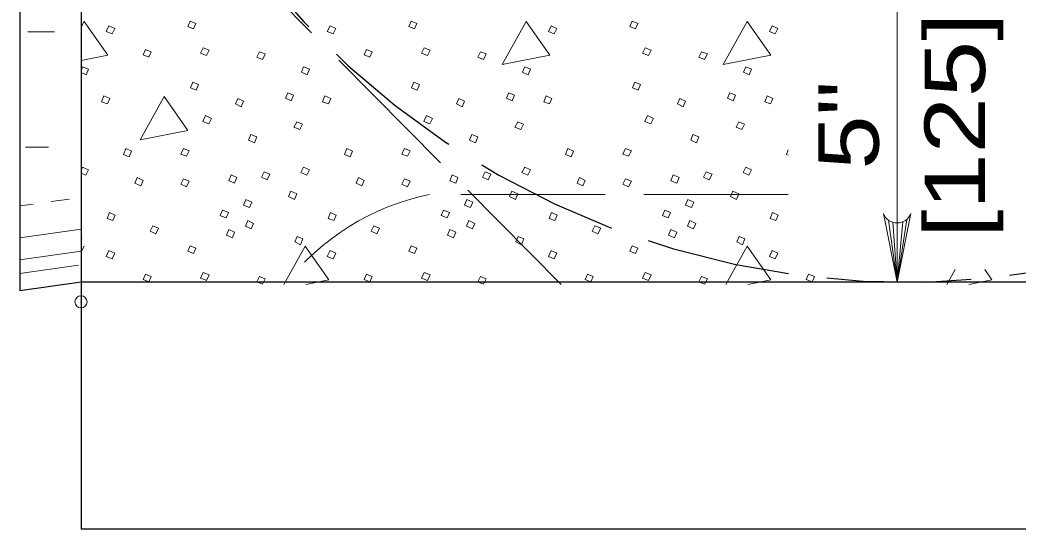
# Model space of a CAD drawing. Extents: x 1036.7 to 1070.7, y 883.9 to 905.9.
# Drawn here: x 1058.066 to 1060.639, y 886.963 to 888.275 of the extents above; entities that cross this region are included whole.
import ezdxf
from ezdxf.enums import TextEntityAlignment as Align

# ---------------------------------------------------------------- set-up
doc = ezdxf.new("R2010")
doc.units = 0
doc.header["$LTSCALE"] = 0.062
doc.header["$PDMODE"] = 32
doc.header["$PDSIZE"] = 0.031
doc.linetypes.add('LONG_DASHED', pattern=[7.5, 6, -1.5])
doc.layers.add('1', color=7, linetype='Continuous', lineweight=13)

msp = doc.modelspace()

# ---------------------------------------------------------------- linework, layer by layer
at = {"layer": '1', "lineweight": 25}
for p, q in [((1058.22342, 892.494), (1058.22342, 886.96275)), ((1058.06608, 891.88667), (1058.06608, 887.57675)), ((1058.22342, 887.59908), (1058.06608, 887.57675)), ((1062.47975, 887.59908), (1058.22342, 887.59908)), ((1062.47975, 886.96275), (1058.22342, 886.96275))]:
    msp.add_line(p, q, dxfattribs=at)
at = {"layer": '1', "linetype": 'LONG_DASHED'}
for p, q in [((1058.22342, 888.84183), (1059.461, 887.59333)), ((1060.0465, 887.82533), (1059.11317, 887.82533))]:
    msp.add_line(p, q, dxfattribs=at)
at = {"layer": '1'}
for p, q in [((1060.32708, 888.49858), (1060.32708, 888.19758)), ((1058.23167, 888.27158), (1058.22342, 888.25683)), ((1058.08675, 888.24467), (1058.15533, 888.24467)), ((1058.68342, 888.19367), (1058.69792, 888.18792)), ((1060.32708, 887.59908), (1060.32708, 888.19758)), ((1058.22342, 888.14475), (1058.22767, 888.15467)), ((1058.08058, 887.94742), (1058.13975, 887.94742)), ((1058.22342, 887.88733), (1058.22767, 887.89583)), ((1058.6105, 887.87583), (1058.61358, 887.87442)), ((1058.19292, 887.81375), (1058.14617, 887.80708)), ((1058.10025, 887.80058), (1058.06608, 887.79575)), ((1058.5885, 887.78492), (1058.58942, 887.78458)), ((1060.30467, 887.75933), (1060.32708, 887.59908)), ((1060.31575, 887.75392), (1060.32708, 887.59908)), ((1060.35183, 887.76117), (1060.32708, 887.59908)), ((1060.3415, 887.75508), (1060.32708, 887.59908)), ((1060.32708, 887.75225), (1060.32708, 887.59908)), ((1058.22342, 887.73558), (1058.06608, 887.71325)), ((1058.22342, 887.67933), (1058.06608, 887.657)), ((1058.23167, 887.69192), (1058.22342, 887.67717)), ((1058.80133, 887.69192), (1058.74633, 887.59333)), ((1059.94083, 887.69192), (1059.88575, 887.59333)), ((1058.21708, 887.64325), (1058.06608, 887.62192)), ((1058.5385, 887.624), (1058.54542, 887.62125)), ((1060.47683, 887.63158), (1060.4555, 887.59333))]:
    msp.add_line(p, q, dxfattribs=at)
for points in [[(1058.22342, 888.17117), (1058.29258, 888.18467), (1058.23167, 888.27158)], [(1058.69708, 888.18492), (1058.69142, 888.17367), (1058.67642, 888.17967), (1058.68342, 888.19367)], [(1058.69792, 888.18792), (1058.69842, 888.18767), (1058.69717, 888.18508), (1058.69708, 888.18492)], [(1058.22767, 888.15467), (1058.24267, 888.14867), (1058.23667, 888.13367), (1058.22342, 888.13983)], [(1058.22342, 888.00725), (1058.22467, 888.00675), (1058.22342, 888.00425)], [(1060.0465, 887.92692), (1060.04175, 887.92883), (1060.0465, 887.94058)], [(1058.22767, 887.89583), (1058.24267, 887.88883), (1058.23567, 887.87483), (1058.22342, 887.88058)], [(1058.60942, 887.85883), (1058.6045, 887.86083), (1058.6105, 887.87583)], [(1058.61358, 887.87442), (1058.62542, 887.86883), (1058.61942, 887.85483), (1058.60942, 887.85883)], [(1058.58542, 887.76975), (1058.5825, 887.77092), (1058.5885, 887.78492)], [(1058.58942, 887.78458), (1058.6035, 887.77892), (1058.5975, 887.76492), (1058.58542, 887.76975)], [(1060.3625, 887.77608), (1060.32708, 887.59908), (1060.29167, 887.77608)], [(1058.22342, 887.71183), (1058.22567, 887.71092), (1058.22342, 887.70533)], [(1058.80258, 887.59333), (1058.86233, 887.605), (1058.80133, 887.69192)], [(1059.94208, 887.59333), (1060.00183, 887.605), (1059.94083, 887.69192)], [(1058.54133, 887.60608), (1058.5315, 887.61), (1058.5385, 887.624)], [(1060.51183, 887.59333), (1060.5715, 887.605), (1060.55292, 887.63158)], [(1058.54542, 887.62125), (1058.5535, 887.618), (1058.5465, 887.604), (1058.54133, 887.60608)]]:
    msp.add_lwpolyline(points, dxfattribs=at)
for points in [[(1058.5045, 888.27258), (1058.5195, 888.26658), (1058.5135, 888.25258), (1058.4985, 888.25858)], [(1059.07425, 888.27258), (1059.08925, 888.26658), (1059.08325, 888.25258), (1059.06825, 888.25858)], [(1059.37108, 888.27158), (1059.30917, 888.16067), (1059.43208, 888.18467)], [(1059.644, 888.27258), (1059.659, 888.26658), (1059.653, 888.25258), (1059.638, 888.25858)], [(1059.94083, 888.27158), (1059.87883, 888.16067), (1060.00183, 888.18467)], [(1058.29558, 888.26058), (1058.31058, 888.25358), (1058.30358, 888.23958), (1058.28858, 888.24558)], [(1058.86533, 888.26058), (1058.88033, 888.25358), (1058.87333, 888.23958), (1058.85833, 888.24558)], [(1059.43508, 888.26058), (1059.45008, 888.25358), (1059.44308, 888.23958), (1059.42808, 888.24558)], [(1060.00483, 888.26058), (1060.01983, 888.25358), (1060.01283, 888.23958), (1059.99783, 888.24558)], [(1058.38958, 888.19967), (1058.40458, 888.19367), (1058.39858, 888.17967), (1058.38358, 888.18567)], [(1058.5385, 888.20367), (1058.5535, 888.19767), (1058.5465, 888.18367), (1058.5315, 888.18967)], [(1058.95933, 888.19967), (1058.97433, 888.19367), (1058.96833, 888.17967), (1058.95333, 888.18567)], [(1059.10825, 888.20367), (1059.12325, 888.19767), (1059.11625, 888.18367), (1059.10125, 888.18967)], [(1059.25317, 888.19367), (1059.26817, 888.18767), (1059.26117, 888.17367), (1059.24617, 888.17967)], [(1059.67792, 888.20367), (1059.69292, 888.19767), (1059.68592, 888.18367), (1059.671, 888.18967)], [(1059.82292, 888.19367), (1059.83792, 888.18767), (1059.83092, 888.17367), (1059.81592, 888.17967)], [(1058.79733, 888.15467), (1058.81233, 888.14867), (1058.80633, 888.13367), (1058.79142, 888.14067)], [(1059.36708, 888.15467), (1059.38208, 888.14867), (1059.37608, 888.13367), (1059.36108, 888.14067)], [(1059.93683, 888.15467), (1059.95183, 888.14867), (1059.94583, 888.13367), (1059.93083, 888.14067)], [(1058.5115, 888.11467), (1058.5265, 888.10867), (1058.5205, 888.09467), (1058.5055, 888.10067)], [(1059.08125, 888.11467), (1059.09625, 888.10867), (1059.09025, 888.09467), (1059.07525, 888.10067)], [(1059.651, 888.11467), (1059.666, 888.10867), (1059.66, 888.09467), (1059.645, 888.10067)], [(1058.75642, 888.08767), (1058.77142, 888.08167), (1058.76542, 888.06675), (1058.75042, 888.07375)], [(1059.32608, 888.08767), (1059.34108, 888.08167), (1059.33508, 888.06675), (1059.32017, 888.07375)], [(1059.89583, 888.08767), (1059.91083, 888.08167), (1059.90483, 888.06675), (1059.88983, 888.07375)], [(1058.28258, 888.07967), (1058.29758, 888.07275), (1058.29158, 888.05875), (1058.27658, 888.06475)], [(1058.4375, 888.07775), (1058.37558, 887.96675), (1058.4985, 887.99075)], [(1058.62742, 888.07275), (1058.64242, 888.06575), (1058.63642, 888.05175), (1058.62142, 888.05875)], [(1058.85233, 888.07967), (1058.86733, 888.07275), (1058.86133, 888.05875), (1058.84633, 888.06475)], [(1059.19717, 888.07275), (1059.21217, 888.06575), (1059.20617, 888.05175), (1059.19117, 888.05875)], [(1059.42208, 888.07967), (1059.43708, 888.07275), (1059.43108, 888.05875), (1059.41608, 888.06475)], [(1059.76692, 888.07275), (1059.78192, 888.06575), (1059.77592, 888.05175), (1059.76092, 888.05875)], [(1059.99183, 888.07967), (1060.00683, 888.07275), (1060.00083, 888.05875), (1059.98583, 888.06475)], [(1058.5445, 888.02875), (1058.5595, 888.02175), (1058.5525, 888.00775), (1058.5375, 888.01375)], [(1058.77942, 888.01275), (1058.79433, 888.00675), (1058.78742, 887.99275), (1058.77242, 887.99875)], [(1059.11425, 888.02875), (1059.12925, 888.02175), (1059.12225, 888.00775), (1059.10725, 888.01375)], [(1059.34908, 888.01275), (1059.36408, 888.00675), (1059.35708, 887.99275), (1059.34208, 887.99875)], [(1059.68392, 888.02875), (1059.69892, 888.02175), (1059.69192, 888.00775), (1059.67692, 888.01375)], [(1059.91883, 888.01275), (1059.93383, 888.00675), (1059.92683, 887.99275), (1059.91183, 887.99875)], [(1058.66142, 887.97975), (1058.67642, 887.97375), (1058.67042, 887.95875), (1058.65542, 887.96575)], [(1059.23117, 887.97975), (1059.24617, 887.97375), (1059.24017, 887.95875), (1059.22517, 887.96575)], [(1059.80092, 887.97975), (1059.81592, 887.97375), (1059.80992, 887.95875), (1059.79492, 887.96575)], [(1058.33858, 887.94375), (1058.35358, 887.93675), (1058.34758, 887.92283), (1058.33258, 887.92883)], [(1058.4875, 887.94375), (1058.5025, 887.93775), (1058.4955, 887.92383), (1058.4805, 887.92975)], [(1058.90833, 887.94375), (1058.92333, 887.93675), (1058.91733, 887.92283), (1058.90233, 887.92883)], [(1059.05725, 887.94375), (1059.07225, 887.93775), (1059.06525, 887.92383), (1059.05025, 887.92975)], [(1059.47808, 887.94375), (1059.49308, 887.93675), (1059.48708, 887.92283), (1059.47208, 887.92883)], [(1059.627, 887.94375), (1059.642, 887.93775), (1059.635, 887.92383), (1059.62, 887.92975)], [(1058.69542, 887.88383), (1058.71042, 887.87783), (1058.70342, 887.86283), (1058.68842, 887.86983)], [(1058.79733, 887.89583), (1058.81233, 887.88883), (1058.80533, 887.87483), (1058.79042, 887.88183)], [(1059.26517, 887.88383), (1059.28017, 887.87783), (1059.27317, 887.86283), (1059.25817, 887.86983)], [(1059.36708, 887.89583), (1059.38208, 887.88883), (1059.37508, 887.87483), (1059.36008, 887.88183)], [(1059.83492, 887.88383), (1059.84992, 887.87783), (1059.84292, 887.86283), (1059.82792, 887.86983)], [(1059.93683, 887.89583), (1059.95183, 887.88883), (1059.94483, 887.87483), (1059.92983, 887.88183)], [(1058.36858, 887.86883), (1058.38358, 887.86183), (1058.37758, 887.84783), (1058.36258, 887.85483)], [(1058.4875, 887.86583), (1058.5025, 887.85983), (1058.4955, 887.84483), (1058.4805, 887.85183)], [(1058.93833, 887.86883), (1058.95333, 887.86183), (1058.94733, 887.84783), (1058.93233, 887.85483)], [(1059.05725, 887.86583), (1059.07225, 887.85983), (1059.06525, 887.84483), (1059.05025, 887.85183)], [(1059.18017, 887.87583), (1059.19517, 887.86883), (1059.18917, 887.85483), (1059.17417, 887.86083)], [(1059.508, 887.86883), (1059.523, 887.86183), (1059.517, 887.84783), (1059.50208, 887.85483)], [(1059.627, 887.86583), (1059.642, 887.85983), (1059.635, 887.84483), (1059.62, 887.85183)], [(1059.74992, 887.87583), (1059.76492, 887.86883), (1059.75892, 887.85483), (1059.74392, 887.86083)], [(1058.76442, 887.83383), (1058.77942, 887.82683), (1058.77342, 887.81283), (1058.75842, 887.81983)], [(1059.33408, 887.83383), (1059.34908, 887.82683), (1059.34308, 887.81283), (1059.32808, 887.81983)], [(1059.90383, 887.83383), (1059.91883, 887.82683), (1059.91283, 887.81283), (1059.89783, 887.81983)], [(1058.64842, 887.81283), (1058.66342, 887.80583), (1058.65742, 887.79183), (1058.64242, 887.79783)], [(1059.21817, 887.81283), (1059.23317, 887.80583), (1059.22717, 887.79183), (1059.21217, 887.79783)], [(1059.78792, 887.81283), (1059.80292, 887.80583), (1059.79692, 887.79183), (1059.78192, 887.79783)], [(1058.29658, 887.77892), (1058.31158, 887.77192), (1058.30558, 887.75792), (1058.29058, 887.76392)], [(1058.86633, 887.77892), (1058.88133, 887.77192), (1058.87533, 887.75792), (1058.86033, 887.76392)], [(1059.15817, 887.78492), (1059.17317, 887.77892), (1059.16717, 887.76492), (1059.15217, 887.77092)], [(1059.43608, 887.77892), (1059.45108, 887.77192), (1059.44508, 887.75792), (1059.43008, 887.76392)], [(1059.72792, 887.78492), (1059.74292, 887.77892), (1059.73692, 887.76492), (1059.72192, 887.77092)], [(1060.00583, 887.77892), (1060.02083, 887.77192), (1060.01483, 887.75792), (1059.99983, 887.76392)], [(1058.65342, 887.75792), (1058.66842, 887.75092), (1058.66242, 887.73692), (1058.64742, 887.74392)], [(1059.22317, 887.75792), (1059.23817, 887.75092), (1059.23217, 887.73692), (1059.21717, 887.74392)], [(1059.79292, 887.75792), (1059.80792, 887.75092), (1059.80192, 887.73692), (1059.78692, 887.74392)], [(1058.40858, 887.74492), (1058.42358, 887.73892), (1058.41658, 887.72392), (1058.40158, 887.73092)], [(1058.6045, 887.73492), (1058.61942, 887.72792), (1058.6135, 887.71392), (1058.5985, 887.72092)], [(1058.97825, 887.74492), (1058.99325, 887.73892), (1058.98625, 887.72392), (1058.97125, 887.73092)], [(1059.17417, 887.73492), (1059.18917, 887.72792), (1059.18317, 887.71392), (1059.16817, 887.72092)], [(1059.548, 887.74492), (1059.563, 887.73892), (1059.556, 887.72392), (1059.541, 887.73092)], [(1059.74392, 887.73492), (1059.75892, 887.72792), (1059.75292, 887.71392), (1059.73792, 887.72092)], [(1058.78042, 887.71692), (1058.79542, 887.71092), (1058.78942, 887.69592), (1058.77442, 887.70292)], [(1059.35008, 887.71692), (1059.36508, 887.71092), (1059.35908, 887.69592), (1059.34408, 887.70292)], [(1059.91983, 887.71692), (1059.93483, 887.71092), (1059.92883, 887.69592), (1059.91383, 887.70292)], [(1058.29558, 887.68092), (1058.31058, 887.67392), (1058.30358, 887.65992), (1058.28858, 887.66592)], [(1058.5045, 887.69292), (1058.5195, 887.68692), (1058.5135, 887.67292), (1058.4985, 887.67892)], [(1058.86533, 887.68092), (1058.88033, 887.67392), (1058.87333, 887.65992), (1058.85833, 887.66592)], [(1059.07425, 887.69292), (1059.08925, 887.68692), (1059.08325, 887.67292), (1059.06825, 887.67892)], [(1059.43508, 887.68092), (1059.45008, 887.67392), (1059.44308, 887.65992), (1059.42808, 887.66592)], [(1059.644, 887.69292), (1059.659, 887.68692), (1059.653, 887.67292), (1059.638, 887.67892)], [(1060.00483, 887.68092), (1060.01983, 887.67392), (1060.01283, 887.65992), (1059.99783, 887.66592)], [(1059.10825, 887.624), (1059.12325, 887.618), (1059.11625, 887.604), (1059.10125, 887.61)], [(1059.67792, 887.624), (1059.69292, 887.618), (1059.68592, 887.604), (1059.671, 887.61)], [(1058.38958, 887.62), (1058.40458, 887.614), (1058.39858, 887.6), (1058.38358, 887.606)], [(1058.68342, 887.614), (1058.69842, 887.608), (1058.69142, 887.594), (1058.67642, 887.6)], [(1058.95933, 887.62), (1058.97433, 887.614), (1058.96833, 887.6), (1058.95333, 887.606)], [(1059.25317, 887.614), (1059.26817, 887.608), (1059.26117, 887.594), (1059.24617, 887.6)], [(1059.529, 887.62), (1059.544, 887.614), (1059.538, 887.6), (1059.523, 887.606)], [(1059.82292, 887.614), (1059.83792, 887.608), (1059.83092, 887.594), (1059.81592, 887.6)], [(1060.09875, 887.62), (1060.11375, 887.614), (1060.10775, 887.6), (1060.09275, 887.606)]]:
    msp.add_lwpolyline(points, close=True, dxfattribs=at)
msp.add_arc((1060.32703, 887.79036), 0.0382, 202.08782, 337.91395, dxfattribs=at)
at = {"layer": '1', "linetype": 'LONG_DASHED', "lineweight": 25}
msp.add_ellipse((1060.35006, 889.72842), major_axis=(2.1297, 0), ratio=0.999895, start_param=3.2863203, end_param=8.1610756, dxfattribs=at)
at = {"layer": '1', "linetype": 'LONG_DASHED'}
msp.add_ellipse((1059.24686, 887.21063), major_axis=(-0.62732, 0), ratio=0.999895, start_param=4.9126755, end_param=5.6270065, dxfattribs=at)
at = {"layer": '1'}
msp.add_point((1058.22342, 887.54858), dxfattribs=at)

# ---------------------------------------------------------------- texts
for s, width, p in [('[125]', 1.25, (1060.55367, 888.00392)), ('5"', 1.2, (1060.27967, 888.00396))]:
    msp.add_text(s, height=0.156, rotation=90, dxfattribs=dict(at, width=width)).set_placement(p, align=Align.CENTER)

doc.saveas('drawing.dxf')
